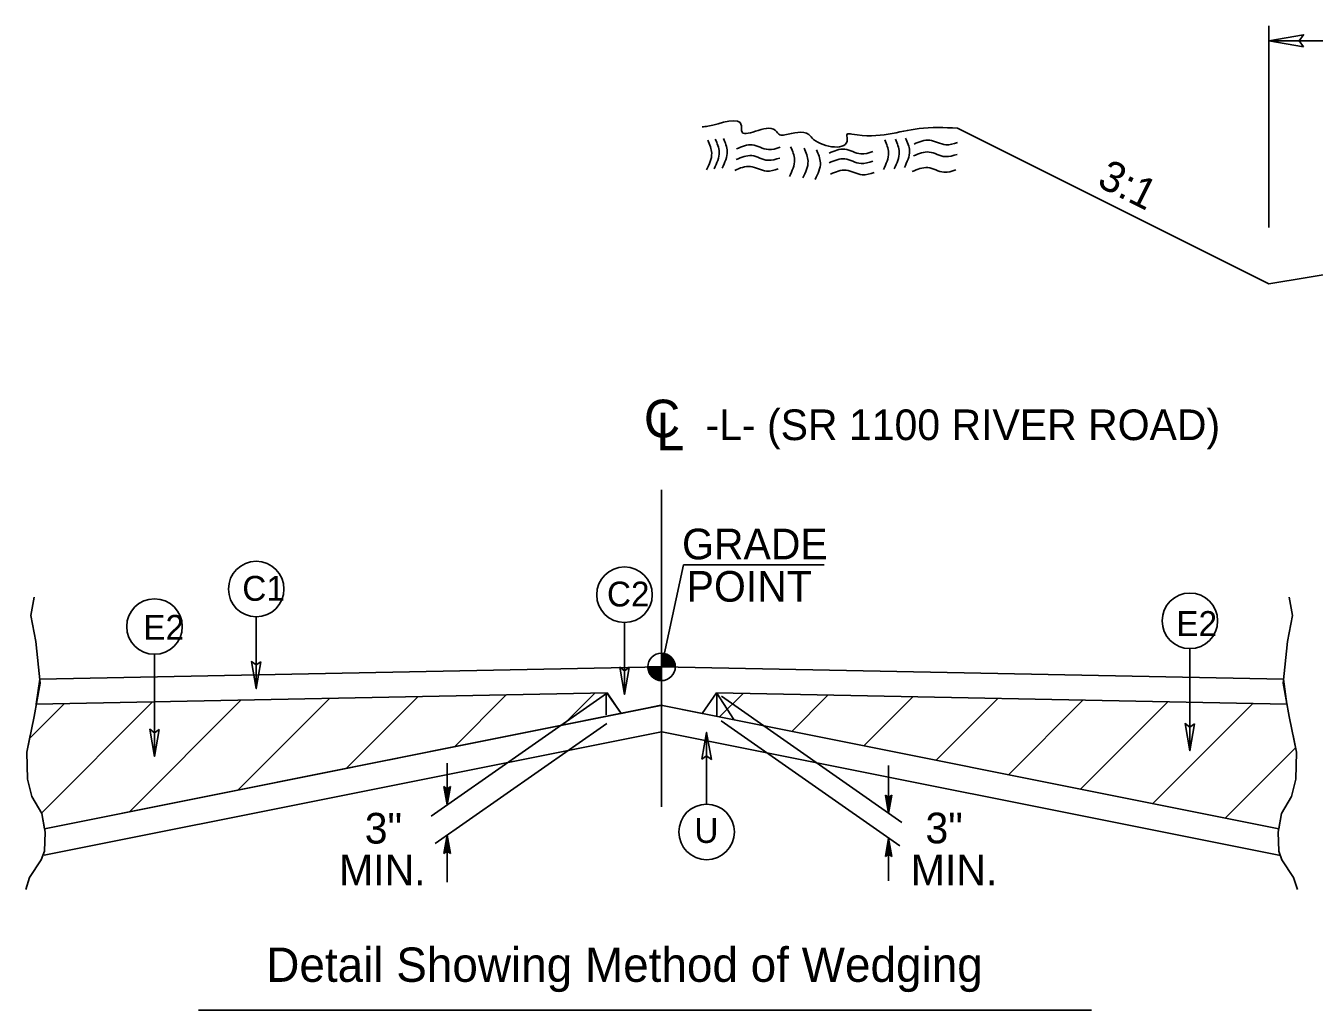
# Model space of a CAD drawing. Extents: x 1734085 to 1734267, y 541107 to 541226.
# Drawn here: x 1734149.56 to 1734191.61, y 541141.44 to 541173.56 of the extents above; entities that cross this region are included whole.
import ezdxf

# ---------------------------------------------------------------- set-up
doc = ezdxf.new("R2010")
doc.units = 0
for name, color, linetype in [('Old_Level_1', 7, 'Continuous'), ('Old_Level_2', 7, 'Continuous'), ('Old_Level_3', 7, 'Continuous'), ('Prop Dimension', 7, 'Continuous'), ('Prop Terminator CELL', 7, 'Continuous'), ('Typical Detail Wedge2 CELL', 7, 'Continuous'), ('Typical ID Circle CELL', 7, 'Continuous'), ('Typical Slope Point Local CELL', 7, 'Continuous'), ('Typical Terminator CELL', 7, 'Continuous'), ('Typical Text Centerline CELL', 7, 'Continuous'), ('Typical Text General CELL', 7, 'Continuous'), ('Typical Text ID Circle CELL', 7, 'Continuous'), ('Typical Text Label CELL', 7, 'Continuous')]:
    doc.layers.add(name, color=color, linetype=linetype)

msp = doc.modelspace()

# ---------------------------------------------------------------- linework, layer by layer
at = {"layer": 'Old_Level_1'}
for p, q in [((1734170.313, 541152.645), (1734170.313, 541153.092)), ((1734169.865, 541152.645), (1734170.313, 541152.645)), ((1734170.312, 541152.197), (1734170.313, 541152.645)), ((1734170.313, 541152.645), (1734170.312, 541152.197)), ((1734170.761, 541152.645), (1734170.313, 541152.645))]:
    msp.add_line(p, q, dxfattribs=at)
for points in [[(1734170.317, 541153.092), (1734170.317, 541153.092), (1734170.317, 541152.645)], [(1734170.326, 541153.092), (1734170.326, 541152.645)], [(1734170.335, 541153.091), (1734170.335, 541152.645)], [(1734170.344, 541153.091), (1734170.344, 541152.645)], [(1734170.353, 541153.09), (1734170.353, 541152.645)], [(1734170.362, 541153.089), (1734170.362, 541152.645)], [(1734170.371, 541153.088), (1734170.371, 541152.645)], [(1734170.38, 541153.087), (1734170.38, 541152.645)], [(1734170.389, 541153.087), (1734170.389, 541152.645)], [(1734170.398, 541153.085), (1734170.398, 541152.645)], [(1734170.407, 541153.082), (1734170.407, 541152.645)], [(1734170.415, 541153.081), (1734170.415, 541152.645)], [(1734170.424, 541153.079), (1734170.424, 541152.645)], [(1734170.433, 541153.076), (1734170.433, 541152.645)], [(1734170.442, 541153.074), (1734170.442, 541152.645)], [(1734170.451, 541153.071), (1734170.451, 541152.645)], [(1734170.46, 541153.068), (1734170.46, 541152.645)], [(1734170.469, 541153.065), (1734170.469, 541152.645)], [(1734170.478, 541153.061), (1734170.478, 541152.645)], [(1734170.487, 541153.057), (1734170.487, 541152.645)], [(1734170.496, 541153.053), (1734170.496, 541152.645)], [(1734170.505, 541153.049), (1734170.505, 541152.645)], [(1734170.514, 541153.045), (1734170.514, 541152.645)], [(1734170.523, 541153.04), (1734170.523, 541152.645)], [(1734170.532, 541153.035), (1734170.532, 541152.645)], [(1734170.541, 541153.03), (1734170.541, 541152.645)], [(1734170.55, 541153.025), (1734170.55, 541152.645)], [(1734170.559, 541153.019), (1734170.559, 541152.645)], [(1734170.568, 541153.013), (1734170.568, 541152.645)], [(1734170.577, 541153.006), (1734170.577, 541152.645)], [(1734170.586, 541153), (1734170.586, 541152.645)], [(1734170.595, 541152.993), (1734170.595, 541152.645)], [(1734170.604, 541152.985), (1734170.604, 541152.645)], [(1734170.612, 541152.977), (1734170.612, 541152.645)], [(1734170.621, 541152.969), (1734170.621, 541152.645)], [(1734170.63, 541152.96), (1734170.63, 541152.645)], [(1734170.639, 541152.951), (1734170.639, 541152.645)], [(1734170.648, 541152.941), (1734170.648, 541152.645)], [(1734170.657, 541152.93), (1734170.657, 541152.645)], [(1734170.666, 541152.919), (1734170.666, 541152.645)], [(1734170.675, 541152.907), (1734170.675, 541152.645)], [(1734170.684, 541152.894), (1734170.684, 541152.645)], [(1734170.693, 541152.881), (1734170.693, 541152.645)], [(1734170.702, 541152.866), (1734170.702, 541152.645)], [(1734170.711, 541152.85), (1734170.711, 541152.645)], [(1734170.72, 541152.831), (1734170.72, 541152.645)], [(1734170.729, 541152.81), (1734170.729, 541152.645)], [(1734170.738, 541152.785), (1734170.738, 541152.645)], [(1734170.747, 541152.754), (1734170.747, 541152.645)], [(1734170.756, 541152.708), (1734170.756, 541152.645)], [(1734169.867, 541152.645), (1734169.867, 541152.596)], [(1734169.876, 541152.645), (1734169.876, 541152.543)], [(1734169.885, 541152.645), (1734169.885, 541152.512)], [(1734169.894, 541152.645), (1734169.894, 541152.485)], [(1734169.903, 541152.645), (1734169.903, 541152.464)], [(1734169.912, 541152.645), (1734169.912, 541152.445)], [(1734169.921, 541152.645), (1734169.921, 541152.428)], [(1734169.93, 541152.645), (1734169.93, 541152.412)], [(1734169.939, 541152.645), (1734169.939, 541152.398)], [(1734169.948, 541152.645), (1734169.948, 541152.385)], [(1734169.957, 541152.645), (1734169.957, 541152.373)], [(1734169.966, 541152.645), (1734169.966, 541152.362)], [(1734169.975, 541152.645), (1734169.975, 541152.351)], [(1734169.984, 541152.645), (1734169.984, 541152.341)], [(1734169.993, 541152.645), (1734169.993, 541152.331)], [(1734170.002, 541152.645), (1734170.002, 541152.322)], [(1734170.011, 541152.645), (1734170.011, 541152.315)], [(1734170.02, 541152.645), (1734170.02, 541152.307)], [(1734170.029, 541152.645), (1734170.029, 541152.299)], [(1734170.037, 541152.645), (1734170.037, 541152.292)], [(1734170.046, 541152.645), (1734170.046, 541152.285)], [(1734170.055, 541152.645), (1734170.055, 541152.279)], [(1734170.064, 541152.645), (1734170.064, 541152.273)], [(1734170.073, 541152.645), (1734170.073, 541152.267)], [(1734170.082, 541152.645), (1734170.082, 541152.261)], [(1734170.091, 541152.645), (1734170.091, 541152.256)], [(1734170.1, 541152.645), (1734170.1, 541152.251)], [(1734170.109, 541152.645), (1734170.109, 541152.246)], [(1734170.118, 541152.645), (1734170.118, 541152.242)], [(1734170.127, 541152.645), (1734170.127, 541152.238)], [(1734170.136, 541152.645), (1734170.136, 541152.234)], [(1734170.145, 541152.645), (1734170.145, 541152.23)], [(1734170.154, 541152.645), (1734170.154, 541152.226)], [(1734170.163, 541152.645), (1734170.163, 541152.223)], [(1734170.172, 541152.645), (1734170.172, 541152.22)], [(1734170.181, 541152.645), (1734170.181, 541152.217)], [(1734170.19, 541152.645), (1734170.19, 541152.215)], [(1734170.199, 541152.645), (1734170.199, 541152.212)], [(1734170.208, 541152.645), (1734170.208, 541152.21)], [(1734170.217, 541152.645), (1734170.217, 541152.208)], [(1734170.225, 541152.645), (1734170.225, 541152.206)], [(1734170.234, 541152.645), (1734170.234, 541152.204)], [(1734170.243, 541152.645), (1734170.243, 541152.203)], [(1734170.252, 541152.645), (1734170.252, 541152.201)], [(1734170.261, 541152.645), (1734170.261, 541152.2)], [(1734170.27, 541152.645), (1734170.27, 541152.199)], [(1734170.279, 541152.645), (1734170.279, 541152.198)], [(1734170.288, 541152.645), (1734170.288, 541152.198)], [(1734170.297, 541152.645), (1734170.297, 541152.197)], [(1734170.306, 541152.645), (1734170.306, 541152.197), (1734170.306, 541152.197)]]:
    msp.add_lwpolyline(points, dxfattribs=at)
msp.add_circle((1734170.312, 541152.645), 0.448, dxfattribs=at)
for start, end in [(359.9905, 89.9905), (179.9905, 269.9905)]:
    msp.add_arc((1734170.312, 541152.645), 0.448, start, end, dxfattribs=at)
at = {"layer": 'Old_Level_2'}
for points in [[(1734171.638, 541170.263), (1734171.824, 541170.285), (1734172.92, 541170.298), (1734172.922, 541170.141), (1734174.019, 541170.154), (1734174.177, 541169.999), (1734174.334, 541170.001), (1734175.117, 541170.01), (1734175.275, 541169.855), (1734176.372, 541169.868), (1734176.37, 541170.024), (1734176.526, 541170.026), (1734178.717, 541170.208), (1734179.966, 541170.223)], [(1734171.821, 541169.824), (1734171.948, 541169.404), (1734171.779, 541168.858)], [(1734172.066, 541169.862), (1734172.194, 541169.442), (1734172.024, 541168.896)], [(1734172.329, 541169.882), (1734172.456, 541169.463), (1734172.287, 541168.917)], [(1734172.763, 541169.545), (1734173.27, 541169.674), (1734173.798, 541169.522), (1734174.183, 541169.597)], [(1734174.525, 541169.609), (1734174.653, 541169.19), (1734174.484, 541168.644)], [(1734174.964, 541169.562), (1734175.092, 541169.142), (1734174.923, 541168.596)], [(1734175.782, 541169.405), (1734176.289, 541169.533), (1734176.817, 541169.381), (1734177.203, 541169.456)], [(1734177.593, 541169.838), (1734177.72, 541169.418), (1734177.551, 541168.872)], [(1734177.943, 541169.86), (1734178.071, 541169.44), (1734177.902, 541168.894)], [(1734178.276, 541169.898), (1734178.404, 541169.479), (1734178.235, 541168.933)], [(1734178.551, 541169.7), (1734179.058, 541169.829), (1734179.586, 541169.677), (1734179.971, 541169.751)], [(1734172.749, 541169.194), (1734173.257, 541169.323), (1734173.785, 541169.171), (1734174.17, 541169.245)], [(1734175.368, 541169.514), (1734175.496, 541169.094), (1734175.327, 541168.548)], [(1734175.786, 541169.089), (1734176.293, 541169.217), (1734176.821, 541169.066), (1734177.206, 541169.14)], [(1734178.538, 541169.314), (1734179.045, 541169.442), (1734179.573, 541169.29), (1734179.958, 541169.365)], [(1734172.701, 541168.843), (1734173.208, 541168.971), (1734173.736, 541168.819), (1734174.121, 541168.894)], [(1734175.825, 541168.721), (1734176.332, 541168.849), (1734176.86, 541168.698), (1734177.246, 541168.772)], [(1734178.491, 541168.804), (1734178.998, 541168.933), (1734179.526, 541168.781), (1734179.912, 541168.856)]]:
    msp.add_spline(points, degree=3, dxfattribs=at)
at = {"layer": 'Prop Dimension'}
for p, q in [((1734190.135, 541166.983), (1734190.135, 541173.56)), ((1734190.135, 541173.068), (1734198.135, 541173.068)), ((1734171.024, 541155.979), (1734170.313, 541152.645)), ((1734171.024, 541155.979), (1734175.618, 541155.979))]:
    msp.add_line(p, q, dxfattribs=at)
at = {"layer": 'Prop Terminator CELL'}
msp.add_lwpolyline([(1734191.26, 541172.874), (1734190.135, 541173.068), (1734191.266, 541173.268), (1734191.122, 541173.068)], close=True, dxfattribs=at)
at = {"layer": 'Typical Detail Wedge2 CELL'}
for p, q in [((1734170.314, 541148.077), (1734170.314, 541158.416)), ((1734170.313, 541152.645), (1734150.022, 541152.24)), ((1734150.022, 541152.24), (1734170.313, 541152.645)), ((1734170.313, 541152.645), (1734190.606, 541152.24)), ((1734170.315, 541152.645), (1734190.606, 541152.24)), ((1734149.906, 541151.424), (1734150.022, 541152.24)), ((1734190.606, 541152.24), (1734190.722, 541151.424)), ((1734149.692, 541150.321), (1734150.813, 541151.442)), ((1734168.533, 541151.797), (1734149.906, 541151.424)), ((1734168.533, 541151.797), (1734149.906, 541151.424)), ((1734150.077, 541147.878), (1734153.699, 541151.5)), ((1734152.944, 541147.917), (1734156.585, 541151.558)), ((1734156.48, 541148.624), (1734159.471, 541151.616)), ((1734160.016, 541149.331), (1734162.357, 541151.673)), ((1734168.51, 541151.782), (1734162.793, 541147.777)), ((1734163.551, 541150.039), (1734165.244, 541151.731)), ((1734167.087, 541150.746), (1734168.13, 541151.789)), ((1734168.507, 541151.789), (1734168.507, 541151.082)), ((1734168.989, 541151.128), (1734168.533, 541151.797)), ((1734168.533, 541151.775), (1734168.989, 541151.128)), ((1734172.109, 541151.797), (1734171.638, 541151.128)), ((1734172.109, 541151.797), (1734171.638, 541151.128)), ((1734172.079, 541151.782), (1734172.108, 541151.78)), ((1734172.109, 541151.797), (1734190.722, 541151.424)), ((1734190.722, 541151.424), (1734172.109, 541151.797)), ((1734172.671, 541150.929), (1734172.12, 541151.789)), ((1734172.12, 541151.789), (1734172.12, 541151.01)), ((1734172.204, 541151.013), (1734172.97, 541151.779)), ((1734172.264, 541151.688), (1734178.154, 541147.563)), ((1734174.561, 541150.542), (1734175.743, 541151.724)), ((1734176.918, 541150.07), (1734178.516, 541151.668)), ((1734179.275, 541149.599), (1734181.289, 541151.613)), ((1734181.632, 541149.127), (1734184.062, 541151.558)), ((1734183.989, 541148.656), (1734186.835, 541151.502)), ((1734186.346, 541148.184), (1734189.608, 541151.447)), ((1734170.344, 541151.397), (1734150.174, 541147.363)), ((1734170.314, 541151.391), (1734150.174, 541147.363)), ((1734170.283, 541151.397), (1734168.989, 541151.128)), ((1734170.283, 541151.397), (1734190.454, 541147.363)), ((1734171.638, 541151.128), (1734170.283, 541151.397)), ((1734170.283, 541151.397), (1734190.454, 541147.363)), ((1734168.523, 541150.803), (1734162.929, 541146.886)), ((1734172.255, 541150.887), (1734178.088, 541146.803)), ((1734170.306, 541150.529), (1734150.167, 541146.501)), ((1734170.321, 541150.529), (1734190.507, 541146.491)), ((1734188.703, 541147.713), (1734190.998, 541150.008)), ((1734162.073, 541149.743), (1734161.437, 541149.615)), ((1734163.313, 541149.503), (1734163.313, 541148.143)), ((1734177.723, 541149.424), (1734177.723, 541147.865)), ((1734163.313, 541148.143), (1734163.208, 541148.739)), ((1734163.313, 541148.661), (1734163.208, 541148.739)), ((1734163.313, 541148.143), (1734163.223, 541148.728)), ((1734163.238, 541148.716), (1734163.313, 541148.143)), ((1734163.313, 541148.143), (1734163.253, 541148.706)), ((1734163.269, 541148.695), (1734163.313, 541148.143)), ((1734163.313, 541148.143), (1734163.284, 541148.684)), ((1734163.299, 541148.672), (1734163.313, 541148.143)), ((1734163.313, 541148.143), (1734163.419, 541148.739)), ((1734163.419, 541148.739), (1734163.313, 541148.661)), ((1734163.405, 541148.728), (1734163.313, 541148.143)), ((1734163.313, 541148.143), (1734163.388, 541148.716)), ((1734163.373, 541148.706), (1734163.313, 541148.143)), ((1734163.313, 541148.143), (1734163.358, 541148.695)), ((1734163.343, 541148.684), (1734163.313, 541148.143)), ((1734163.313, 541148.143), (1734163.328, 541148.672)), ((1734163.313, 541148.661), (1734163.313, 541148.143)), ((1734177.723, 541147.865), (1734177.618, 541148.462)), ((1734177.723, 541148.384), (1734177.618, 541148.462)), ((1734177.723, 541147.865), (1734177.633, 541148.451)), ((1734177.648, 541148.44), (1734177.723, 541147.865)), ((1734177.723, 541147.865), (1734177.663, 541148.429)), ((1734177.678, 541148.417), (1734177.723, 541147.865)), ((1734177.723, 541147.865), (1734177.693, 541148.407)), ((1734177.708, 541148.396), (1734177.723, 541147.865)), ((1734177.723, 541147.865), (1734177.829, 541148.462)), ((1734177.829, 541148.462), (1734177.723, 541148.384)), ((1734177.813, 541148.451), (1734177.723, 541147.865)), ((1734177.723, 541147.865), (1734177.798, 541148.44)), ((1734177.783, 541148.429), (1734177.723, 541147.865)), ((1734177.723, 541147.865), (1734177.768, 541148.417)), ((1734177.753, 541148.407), (1734177.723, 541147.865)), ((1734177.723, 541147.865), (1734177.738, 541148.396)), ((1734177.723, 541148.384), (1734177.723, 541147.865)), ((1734163.313, 541147.155), (1734163.208, 541146.558)), ((1734163.223, 541146.57), (1734163.313, 541147.155)), ((1734163.313, 541147.155), (1734163.238, 541146.581)), ((1734163.253, 541146.593), (1734163.313, 541147.155)), ((1734163.313, 541147.155), (1734163.269, 541146.603)), ((1734163.284, 541146.614), (1734163.313, 541147.155)), ((1734163.313, 541147.155), (1734163.299, 541146.625)), ((1734163.313, 541147.155), (1734163.313, 541145.624)), ((1734163.313, 541147.155), (1734163.419, 541146.558)), ((1734163.313, 541146.636), (1734163.313, 541147.155)), ((1734163.328, 541146.625), (1734163.313, 541147.155)), ((1734163.313, 541147.155), (1734163.343, 541146.614)), ((1734163.358, 541146.603), (1734163.313, 541147.155)), ((1734163.313, 541147.155), (1734163.373, 541146.593)), ((1734163.388, 541146.581), (1734163.313, 541147.155)), ((1734163.313, 541147.155), (1734163.405, 541146.57)), ((1734177.723, 541147.058), (1734177.618, 541146.461)), ((1734177.633, 541146.473), (1734177.723, 541147.058)), ((1734177.723, 541147.058), (1734177.648, 541146.484)), ((1734177.663, 541146.496), (1734177.723, 541147.058)), ((1734177.723, 541147.058), (1734177.678, 541146.506)), ((1734177.693, 541146.517), (1734177.723, 541147.058)), ((1734177.723, 541147.058), (1734177.708, 541146.528)), ((1734177.723, 541147.058), (1734177.723, 541145.663)), ((1734177.723, 541147.058), (1734177.829, 541146.461)), ((1734177.723, 541146.539), (1734177.723, 541147.058)), ((1734177.738, 541146.528), (1734177.723, 541147.058)), ((1734177.723, 541147.058), (1734177.753, 541146.517)), ((1734177.768, 541146.506), (1734177.723, 541147.058)), ((1734177.723, 541147.058), (1734177.783, 541146.496)), ((1734177.798, 541146.484), (1734177.723, 541147.058)), ((1734177.723, 541147.058), (1734177.813, 541146.473)), ((1734163.208, 541146.558), (1734163.313, 541146.636)), ((1734163.313, 541146.636), (1734163.419, 541146.558)), ((1734177.618, 541146.461), (1734177.723, 541146.539)), ((1734177.723, 541146.539), (1734177.829, 541146.461))]:
    msp.add_line(p, q, dxfattribs=at)
for points in [[(1734149.833, 541154.918), (1734149.725, 541154.323), (1734149.887, 541153.478), (1734150.031, 541152.11), (1734149.833, 541151.03), (1734149.6, 541149.86), (1734149.617, 541148.978), (1734149.761, 541148.42), (1734150.086, 541147.862), (1734150.193, 541147.25), (1734150.175, 541146.638), (1734150.067, 541146.35), (1734149.69, 541145.774), (1734149.564, 541145.377)], [(1734190.794, 541154.918), (1734190.902, 541154.323), (1734190.74, 541153.478), (1734190.596, 541152.11), (1734190.794, 541151.03), (1734191.028, 541149.86), (1734191.01, 541148.978), (1734190.865, 541148.42), (1734190.542, 541147.862), (1734190.434, 541147.25), (1734190.451, 541146.638), (1734190.559, 541146.35), (1734190.937, 541145.774), (1734191.063, 541145.377)], [(1734150.173, 541147.363), (1734150.086, 541147.862), (1734149.761, 541148.42), (1734149.617, 541148.978), (1734149.6, 541149.86), (1734149.708, 541150.402)], [(1734190.454, 541147.363), (1734190.542, 541147.862), (1734190.865, 541148.42), (1734191.01, 541148.978), (1734191.028, 541149.86), (1734190.919, 541150.402)]]:
    msp.add_lwpolyline(points, dxfattribs=at)
at = {"layer": 'Typical ID Circle CELL'}
for p, q in [((1734157.084, 541154.278), (1734157.084, 541151.936)), ((1734169.102, 541154.092), (1734169.102, 541151.749)), ((1734187.555, 541153.241), (1734187.555, 541149.91)), ((1734153.766, 541153.055), (1734153.766, 541149.724)), ((1734171.782, 541148.167), (1734171.782, 541150.509))]:
    msp.add_line(p, q, dxfattribs=at)
for centre in [(1734157.084, 541155.184), (1734169.102, 541154.998), (1734153.765, 541153.961), (1734187.554, 541154.147), (1734171.782, 541147.26)]:
    msp.add_circle(centre, 0.906, dxfattribs=at)
at = {"layer": 'Typical Slope Point Local CELL'}
for p in [(1734179.966, 541170.223), (1734198.13, 541166.474)]:
    msp.add_line(p, (1734190.13, 541165.141), dxfattribs=at)
at = {"layer": 'Typical Terminator CELL'}
for points in [[(1734157.235, 541152.815), (1734157.084, 541151.936), (1734156.928, 541152.819), (1734157.084, 541152.707)], [(1734157.235, 541152.815), (1734157.084, 541151.936), (1734156.928, 541152.819), (1734157.084, 541152.707)], [(1734169.253, 541152.628), (1734169.102, 541151.749), (1734168.946, 541152.633), (1734169.102, 541152.521)], [(1734169.253, 541152.628), (1734169.102, 541151.749), (1734168.946, 541152.633), (1734169.102, 541152.521)], [(1734153.917, 541150.603), (1734153.766, 541149.724), (1734153.61, 541150.608), (1734153.766, 541150.496)], [(1734153.917, 541150.603), (1734153.766, 541149.724), (1734153.61, 541150.608), (1734153.766, 541150.496)], [(1734187.706, 541150.789), (1734187.555, 541149.91), (1734187.398, 541150.794), (1734187.555, 541150.681)], [(1734171.63, 541149.63), (1734171.782, 541150.509), (1734171.938, 541149.625), (1734171.782, 541149.738)], [(1734171.63, 541149.63), (1734171.782, 541150.509), (1734171.938, 541149.625), (1734171.782, 541149.738)]]:
    msp.add_lwpolyline(points, close=True, dxfattribs=at)
at = {"layer": 'Typical Text Label CELL'}
msp.add_line((1734155.202, 541141.444), (1734184.347, 541141.444), dxfattribs=at)

# ---------------------------------------------------------------- texts
at = {"layer": 'Old_Level_3'}
for s, p in [('GRADE', (1734170.98, 541156.154)), ('POINT', (1734171.13, 541154.772))]:
    msp.add_text(s, height=1, dxfattribs=at).set_placement(p)
at = {"layer": 'Typical Detail Wedge2 CELL'}
for s, p in [('3"', (1734160.626, 541146.881)), ('3"', (1734178.925, 541146.889)), ('MIN.', (1734159.788, 541145.522)), ('MIN.', (1734178.445, 541145.522))]:
    msp.add_text(s, height=1, dxfattribs=at).set_placement(p)
at = {"layer": 'Typical Slope Point Local CELL'}
msp.add_text('3:1', height=1, rotation=333.435, dxfattribs=at).set_placement((1734184.483, 541168.347))
at = {"layer": 'Typical Text Centerline CELL'}
for s, height, p in [('C', 1.23, (1734169.733, 541160.132)), ('-L- (SR 1100 RIVER ROAD)', 1, (1734171.747, 541160.043))]:
    msp.add_text(s, height=height, dxfattribs=at).set_placement(p)
msp.add_text('L', height=1.231, rotation=359.9469, dxfattribs=at).set_placement((1734170.142, 541159.712))
at = {"layer": 'Typical Text General CELL'}
msp.add_text('Detail Showing Method of Wedging', height=1.11936, dxfattribs=at).set_placement((1734157.412, 541142.37))
at = {"layer": 'Typical Text ID Circle CELL'}
for s, height, p in [('C1', 0.8112, (1734156.63, 541154.801)), ('C2', 0.8112, (1734168.531, 541154.615)), ('E2', 0.8112, (1734187.114, 541153.653)), ('E2', 0.8112, (1734153.402, 541153.529)), ('U', 0.811, (1734171.386, 541146.902))]:
    msp.add_text(s, height=height, dxfattribs=at).set_placement(p)

doc.saveas('drawing.dxf')
